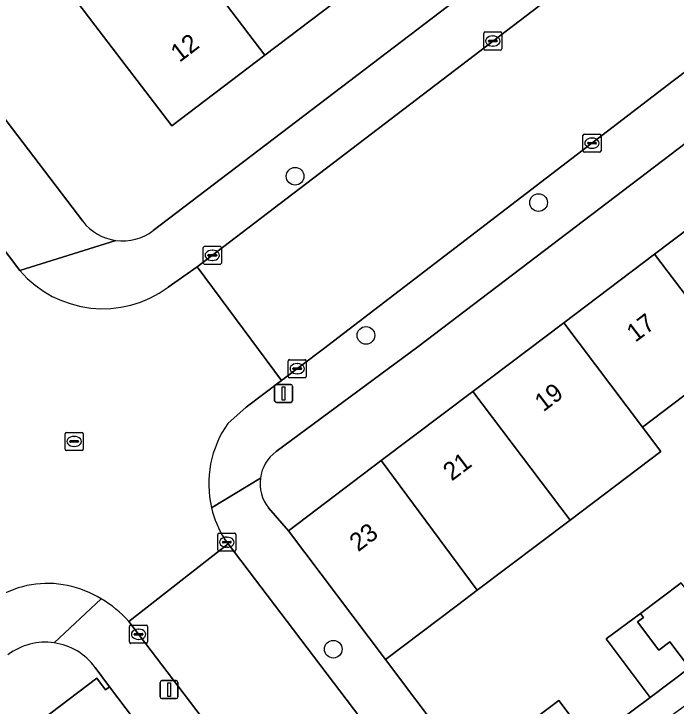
# Model space of a CAD drawing. Extents: x 160030 to 160839, y 385325 to 386450.
# Drawn here: x 160433.9 to 160470.59, y 385780.35 to 385818.69 of the extents above; entities that cross this region are included whole.
import ezdxf

# ---------------------------------------------------------------- set-up
doc = ezdxf.new("R2010")
doc.units = 0
for name, color, linetype in [('IMGEO_Boom', 7, 'Continuous'), ('IMGEO_Erf', 7, 'Continuous'), ('IMGEO_Kolk', 7, 'Continuous'), ('IMGEO_Lichtmast', 7, 'Continuous'), ('IMGEO_Muur', 7, 'Continuous'), ('IMGEO_Pand', 7, 'Continuous'), ('IMGEO_Pand_nummerreeks', 7, 'Continuous'), ('IMGEO_Rijbaan_lokaal_gesloten', 7, 'Continuous'), ('IMGEO_Rijbaan_lokaal_open', 7, 'Continuous'), ('IMGEO_Rioolput', 7, 'Continuous'), ('IMGEO_Voetpad_open', 7, 'Continuous')]:
    doc.layers.add(name, color=color, linetype=linetype)

msp = doc.modelspace()

# ---------------------------------------------------------------- linework, layer by layer
at = {"layer": 'IMGEO_Boom'}
for centre in [(160449.48, 385809.696), (160462.963, 385808.239), (160453.405, 385800.885), (160451.596, 385783.509)]:
    msp.add_circle(centre, 0.489, dxfattribs=at)
at = {"layer": 'IMGEO_Erf'}
for points in [[(160467.463, 385842.567), (160469.844, 385844.381), (160463.561, 385852.624), (160458.547, 385848.802), (160460.94, 385845.697), (160458.995, 385844.199), (160456.333, 385842.148), (160453.941, 385845.253), (160448.054, 385840.924), (160450.43, 385837.841), (160448.874, 385836.653), (160446.135, 385834.562), (160443.773, 385837.627), (160438.306, 385833.163), (160440.377, 385830.449), (160438.706, 385829.174), (160433.311, 385825.057), (160431.24, 385827.77), (160425.422, 385823.334), (160437.717, 385807.206)], [(160502.255, 385835.22), (160500, 385833.506), (160456.281, 385800.253), (160448.431, 385794.458)], [(160441.615, 385806.689), (160475.467, 385832.462)], [(160452.895, 385820.284), (160447.811, 385816.411), (160442.656, 385812.482), (160438.396, 385818.072), (160437.33, 385819.471)], [(160447.999, 385791.331), (160449.109, 385790.064), (160454.255, 385793.952), (160459.32, 385797.779), (160464.358, 385801.585), (160469.393, 385805.39), (160474.571, 385809.302)], [(160473.754, 385799.618), (160468.72, 385795.811), (160469.74, 385794.448), (160464.707, 385790.65), (160459.571, 385786.773), (160458.479, 385785.949), (160454.488, 385782.937), (160457.798, 385778.545), (160459.045, 385776.888), (160464.083, 385780.673), (160465.818, 385778.364), (160469.15, 385780.836), (160466.716, 385784.074), (160468.603, 385785.493), (160470.862, 385787.192)], [(160432.251, 385777.109), (160432.774, 385776.42), (160434.275, 385777.561), (160435.973, 385778.852), (160435.427, 385779.57), (160438.493, 385781.901), (160438.986, 385781.253), (160439.203, 385781.418), (160438.405, 385782.504)]]:
    msp.add_lwpolyline(points, dxfattribs=at)
for centre, radius, start, end in [((160439.928, 385808.909), 2.79, 217.6113, 262.4111), ((160439.926, 385808.905), 2.786, 262.4288, 307.3161), ((160449.754, 385792.68), 2.216, 126.6579, 172.092), ((160449.757, 385792.684), 2.218, 172.2024, 217.5914), ((160435.648, 385780.463), 3.434, 81.858, 127.1706), ((160435.647, 385780.47), 3.426, 36.4076, 81.8358)]:
    msp.add_arc(centre, radius, start, end, dxfattribs=at)
at = {"layer": 'IMGEO_Kolk'}
for p, q in [((160459.931, 385816.759), (160459.931, 385817.611)), ((160460.006, 385817.685), (160460.858, 385817.685)), ((160460.419, 385817.465), (160460.444, 385817.465)), ((160460.932, 385817.611), (160460.932, 385816.759)), ((160460.19, 385817.179), (160460.19, 385817.191)), ((160460.628, 385817.142), (160460.23, 385817.142)), ((160460.233, 385817.228), (160460.631, 385817.228)), ((160460.674, 385817.191), (160460.674, 385817.179)), ((160460.858, 385816.685), (160460.006, 385816.685)), ((160460.442, 385816.905), (160460.417, 385816.905)), ((160465.422, 385811.103), (160465.422, 385811.955)), ((160465.497, 385812.029), (160466.349, 385812.029)), ((160466.423, 385811.955), (160466.423, 385811.103)), ((160465.724, 385811.572), (160466.122, 385811.572)), ((160465.91, 385811.809), (160465.935, 385811.809)), ((160465.681, 385811.523), (160465.681, 385811.535)), ((160466.119, 385811.486), (160465.721, 385811.486)), ((160465.933, 385811.249), (160465.908, 385811.249)), ((160466.165, 385811.535), (160466.165, 385811.523)), ((160466.349, 385811.029), (160465.497, 385811.029)), ((160444.469, 385805.819), (160445.321, 385805.819)), ((160444.394, 385804.893), (160444.394, 385805.745)), ((160444.882, 385805.599), (160444.907, 385805.599)), ((160445.395, 385805.745), (160445.395, 385804.893)), ((160444.653, 385805.313), (160444.653, 385805.325)), ((160445.091, 385805.276), (160444.693, 385805.276)), ((160444.696, 385805.362), (160445.094, 385805.362)), ((160444.905, 385805.039), (160444.88, 385805.039)), ((160445.137, 385805.325), (160445.137, 385805.313)), ((160445.321, 385804.819), (160444.469, 385804.819)), ((160449.1, 385798.615), (160449.1, 385799.467)), ((160449.175, 385799.541), (160450.027, 385799.541)), ((160449.588, 385799.321), (160449.613, 385799.321)), ((160450.101, 385799.467), (160450.101, 385798.615)), ((160449.359, 385799.035), (160449.359, 385799.047)), ((160449.797, 385798.998), (160449.399, 385798.998)), ((160449.402, 385799.084), (160449.8, 385799.084)), ((160449.843, 385799.047), (160449.843, 385799.035)), ((160450.027, 385798.541), (160449.175, 385798.541)), ((160449.611, 385798.761), (160449.586, 385798.761)), ((160445.201, 385789.007), (160445.201, 385789.859)), ((160445.276, 385789.933), (160446.128, 385789.933)), ((160445.689, 385789.713), (160445.714, 385789.713)), ((160446.202, 385789.859), (160446.202, 385789.007)), ((160445.46, 385789.427), (160445.46, 385789.439)), ((160445.898, 385789.39), (160445.5, 385789.39)), ((160445.503, 385789.476), (160445.901, 385789.476)), ((160445.944, 385789.439), (160445.944, 385789.427)), ((160445.712, 385789.153), (160445.687, 385789.153)), ((160446.128, 385788.933), (160445.276, 385788.933)), ((160440.312, 385783.908), (160440.312, 385784.76)), ((160440.387, 385784.834), (160441.239, 385784.834)), ((160441.313, 385784.76), (160441.313, 385783.908)), ((160440.571, 385784.328), (160440.571, 385784.34)), ((160440.614, 385784.377), (160441.012, 385784.377)), ((160440.8, 385784.614), (160440.825, 385784.614)), ((160441.055, 385784.34), (160441.055, 385784.328)), ((160441.009, 385784.291), (160440.611, 385784.291)), ((160440.823, 385784.054), (160440.798, 385784.054)), ((160441.239, 385783.834), (160440.387, 385783.834))]:
    msp.add_line(p, q, dxfattribs=at)
for points in [[(160459.931, 385816.759), (160459.931, 385817.611)], [(160460.006, 385817.685), (160460.858, 385817.685)], [(160460.932, 385817.611), (160460.932, 385816.759)], [(160460.858, 385816.685), (160460.006, 385816.685)], [(160465.422, 385811.103), (160465.422, 385811.955)], [(160465.497, 385812.029), (160466.349, 385812.029)], [(160466.423, 385811.955), (160466.423, 385811.103)], [(160466.349, 385811.029), (160465.497, 385811.029)], [(160444.469, 385805.819), (160445.321, 385805.819)], [(160444.394, 385804.893), (160444.394, 385805.745)], [(160445.395, 385805.745), (160445.395, 385804.893)], [(160445.321, 385804.819), (160444.469, 385804.819)], [(160449.1, 385798.615), (160449.1, 385799.467)], [(160449.175, 385799.541), (160450.027, 385799.541)], [(160450.101, 385799.467), (160450.101, 385798.615)], [(160450.027, 385798.541), (160449.175, 385798.541)], [(160445.201, 385789.007), (160445.201, 385789.859)], [(160445.276, 385789.933), (160446.128, 385789.933)], [(160446.202, 385789.859), (160446.202, 385789.007)], [(160446.128, 385788.933), (160445.276, 385788.933)], [(160440.312, 385783.908), (160440.312, 385784.76)], [(160440.387, 385784.834), (160441.239, 385784.834)], [(160441.313, 385784.76), (160441.313, 385783.908)], [(160441.239, 385783.834), (160440.387, 385783.834)]]:
    msp.add_lwpolyline(points, dxfattribs=at)
for centre, radius, start, end in [((160460.008, 385817.609), 0.0765, 91.552, 178.448), ((160460.008, 385817.609), 0.0765, 91.552, 178.448), ((160460.856, 385817.609), 0.0765, 1.552, 88.448), ((160460.856, 385817.609), 0.0765, 1.552, 88.448), ((160460.23, 385817.188), 0.0403, 85.8775, 175.7526), ((160460.227, 385817.178), 0.0366, 178.938, 274.7102), ((160460.631, 385817.185), 0.043, 264.8664, 352.4533), ((160460.635, 385817.19), 0.0386, 1.7309, 96.639), ((160460.008, 385816.761), 0.0765, 181.552, 268.448), ((160460.008, 385816.761), 0.0765, 181.552, 268.448), ((160460.856, 385816.761), 0.0765, 271.552, 358.448), ((160460.856, 385816.761), 0.0765, 271.552, 358.448), ((160465.499, 385811.953), 0.0765, 91.552, 178.448), ((160465.499, 385811.953), 0.0765, 91.552, 178.448), ((160466.347, 385811.953), 0.0765, 1.552, 88.448), ((160466.347, 385811.953), 0.0765, 1.552, 88.448), ((160465.721, 385811.532), 0.0403, 85.8775, 175.7526), ((160466.126, 385811.534), 0.0386, 1.7309, 96.639), ((160465.718, 385811.522), 0.0366, 178.938, 274.7102), ((160466.122, 385811.529), 0.043, 264.8664, 352.4533), ((160465.499, 385811.105), 0.0765, 181.552, 268.448), ((160465.499, 385811.105), 0.0765, 181.552, 268.448), ((160466.347, 385811.105), 0.0765, 271.552, 358.448), ((160466.347, 385811.105), 0.0765, 271.552, 358.448), ((160444.471, 385805.743), 0.0765, 91.552, 178.448), ((160444.471, 385805.743), 0.0765, 91.552, 178.448), ((160445.319, 385805.743), 0.0765, 1.552, 88.448), ((160445.319, 385805.743), 0.0765, 1.552, 88.448), ((160444.693, 385805.322), 0.0403, 85.8775, 175.7526), ((160444.69, 385805.312), 0.0366, 178.938, 274.7102), ((160445.094, 385805.319), 0.043, 264.8664, 352.4533), ((160445.098, 385805.324), 0.0386, 1.7309, 96.639), ((160444.471, 385804.895), 0.0765, 181.552, 268.448), ((160444.471, 385804.895), 0.0765, 181.552, 268.448), ((160445.319, 385804.895), 0.0765, 271.552, 358.448), ((160445.319, 385804.895), 0.0765, 271.552, 358.448), ((160449.177, 385799.465), 0.0765, 91.552, 178.448), ((160449.177, 385799.465), 0.0765, 91.552, 178.448), ((160450.025, 385799.465), 0.0765, 1.552, 88.448), ((160450.025, 385799.465), 0.0765, 1.552, 88.448), ((160449.399, 385799.044), 0.0403, 85.8775, 175.7526), ((160449.396, 385799.034), 0.0366, 178.938, 274.7102), ((160449.8, 385799.041), 0.043, 264.8664, 352.4533), ((160449.804, 385799.046), 0.0386, 1.7309, 96.639), ((160449.177, 385798.617), 0.0765, 181.552, 268.448), ((160449.177, 385798.617), 0.0765, 181.552, 268.448), ((160450.025, 385798.617), 0.0765, 271.552, 358.448), ((160450.025, 385798.617), 0.0765, 271.552, 358.448), ((160445.278, 385789.857), 0.0765, 91.552, 178.448), ((160445.278, 385789.857), 0.0765, 91.552, 178.448), ((160446.126, 385789.857), 0.0765, 1.552, 88.448), ((160446.126, 385789.857), 0.0765, 1.552, 88.448), ((160445.5, 385789.436), 0.0403, 85.8775, 175.7526), ((160445.497, 385789.426), 0.0366, 178.938, 274.7102), ((160445.901, 385789.433), 0.043, 264.8664, 352.4533), ((160445.905, 385789.438), 0.0386, 1.7309, 96.639), ((160445.278, 385789.009), 0.0765, 181.552, 268.448), ((160445.278, 385789.009), 0.0765, 181.552, 268.448), ((160446.126, 385789.009), 0.0765, 271.552, 358.448), ((160446.126, 385789.009), 0.0765, 271.552, 358.448), ((160440.389, 385784.758), 0.0765, 91.552, 178.448), ((160440.389, 385784.758), 0.0765, 91.552, 178.448), ((160441.237, 385784.758), 0.0765, 1.552, 88.448), ((160441.237, 385784.758), 0.0765, 1.552, 88.448), ((160440.611, 385784.337), 0.0403, 85.8775, 175.7526), ((160441.016, 385784.339), 0.0386, 1.7309, 96.639), ((160440.608, 385784.327), 0.0366, 178.938, 274.7102), ((160441.012, 385784.334), 0.043, 264.8664, 352.4533), ((160440.389, 385783.91), 0.0765, 181.552, 268.448), ((160440.389, 385783.91), 0.0765, 181.552, 268.448), ((160441.237, 385783.91), 0.0765, 271.552, 358.448), ((160441.237, 385783.91), 0.0765, 271.552, 358.448)]:
    msp.add_arc(centre, radius, start, end, dxfattribs=at)
for centre, major_axis, ratio, start_param, end_param in [((160460.418, 385817.185), (-0.387, 0.002), 0.722429, 4.712389, 7.853982), ((160460.443, 385817.185), (-0.39, 0.002), 0.717154, 1.570796, 4.712389), ((160465.909, 385811.529), (-0.387, 0.002), 0.722429, 4.712389, 7.853982), ((160465.934, 385811.529), (-0.39, 0.002), 0.717154, 1.570796, 4.712389), ((160444.881, 385805.319), (-0.387, 0.002), 0.722429, 4.712389, 7.853982), ((160444.906, 385805.319), (-0.39, 0.002), 0.717154, 1.570796, 4.712389), ((160449.587, 385799.041), (-0.387, 0.002), 0.722429, 4.712389, 7.853982), ((160449.612, 385799.041), (-0.39, 0.002), 0.717154, 1.570796, 4.712389), ((160445.688, 385789.433), (-0.387, 0.002), 0.722429, 4.712389, 7.853982), ((160445.713, 385789.433), (-0.39, 0.002), 0.717154, 1.570796, 4.712389), ((160440.799, 385784.334), (-0.387, 0.002), 0.722429, 4.712389, 7.853982), ((160440.824, 385784.334), (-0.39, 0.002), 0.717154, 1.570796, 4.712389)]:
    msp.add_ellipse(centre, major_axis=major_axis, ratio=ratio, start_param=start_param, end_param=end_param, dxfattribs=at)
at = {"layer": 'IMGEO_Lichtmast'}
for p, q in [((160448.447, 385798.17), (160449.237, 385798.17)), ((160449.237, 385798.17), (160448.447, 385798.17)), ((160448.347, 385797.27), (160448.347, 385798.07)), ((160448.347, 385798.07), (160448.347, 385797.27)), ((160449.337, 385798.07), (160449.337, 385797.27)), ((160449.337, 385797.27), (160449.337, 385798.07)), ((160449.237, 385797.17), (160448.447, 385797.17)), ((160448.447, 385797.17), (160449.237, 385797.17)), ((160442.004, 385780.873), (160442.004, 385781.673)), ((160442.004, 385781.673), (160442.004, 385780.873)), ((160442.104, 385781.773), (160442.894, 385781.773)), ((160442.894, 385781.773), (160442.104, 385781.773)), ((160442.994, 385781.673), (160442.994, 385780.873)), ((160442.994, 385780.873), (160442.994, 385781.673)), ((160442.894, 385780.773), (160442.104, 385780.773)), ((160442.104, 385780.773), (160442.894, 385780.773))]:
    msp.add_line(p, q, dxfattribs=at)
for points in [[(160448.767, 385798.045), (160448.917, 385798.045), (160448.917, 385797.295), (160448.767, 385797.295), (160448.767, 385798.045)], [(160442.424, 385781.648), (160442.574, 385781.648), (160442.574, 385780.898), (160442.424, 385780.898), (160442.424, 385781.648)]]:
    msp.add_lwpolyline(points, dxfattribs=at)
for centre, start, end in [((160448.447, 385798.07), 90, 180), ((160448.447, 385798.07), 90, 180), ((160449.237, 385798.07), 0, 90), ((160449.237, 385798.07), 360, 90), ((160448.447, 385797.27), 180, 270), ((160448.447, 385797.27), 180, 270), ((160449.237, 385797.27), 270, 0), ((160449.237, 385797.27), 270, 0), ((160442.104, 385781.673), 90, 180), ((160442.104, 385781.673), 90, 180), ((160442.894, 385781.673), 0, 90), ((160442.894, 385781.673), 360, 90), ((160442.104, 385780.873), 180, 270), ((160442.104, 385780.873), 180, 270), ((160442.894, 385780.873), 270, 0), ((160442.894, 385780.873), 270, 0)]:
    msp.add_arc(centre, 0.1, start, end, dxfattribs=at)
at = {"layer": 'IMGEO_Muur'}
msp.add_lwpolyline([(160454.488, 385782.937), (160457.798, 385778.545)], dxfattribs=at)
at = {"layer": 'IMGEO_Pand'}
for points in [[(160448.635, 385825.874), (160447.507, 385827.354), (160444.949, 385825.405), (160446.077, 385823.925), (160443.551, 385822), (160447.811, 385816.411), (160452.895, 385820.284)], [(160443.551, 385822), (160442.485, 385823.4), (160442.218, 385823.197), (160440.264, 385825.761), (160435.376, 385822.036), (160437.33, 385819.471), (160438.396, 385818.072), (160442.656, 385812.482), (160447.811, 385816.411)], [(160473.754, 385799.618), (160478.951, 385803.548), (160477.599, 385805.324), (160474.571, 385809.302), (160469.393, 385805.39)], [(160468.72, 385795.811), (160473.754, 385799.618), (160469.393, 385805.39), (160464.358, 385801.585)], [(160464.707, 385790.65), (160469.74, 385794.448), (160468.72, 385795.811), (160464.358, 385801.585), (160459.32, 385797.779)], [(160459.32, 385797.779), (160454.255, 385793.952), (160459.571, 385786.773), (160464.707, 385790.65)], [(160454.488, 385782.937), (160458.479, 385785.949), (160459.571, 385786.773), (160454.255, 385793.952), (160449.109, 385790.064)], [(160468.603, 385785.493), (160468.772, 385785.27), (160468.439, 385785.019), (160469.623, 385783.448), (160470.237, 385783.911), (160471.324, 385782.471), (160473.297, 385783.955), (160470.862, 385787.192)], [(160468.603, 385785.493), (160466.716, 385784.074), (160469.15, 385780.836), (160471.324, 385782.471), (160470.237, 385783.911), (160469.623, 385783.448), (160468.439, 385785.019), (160468.772, 385785.27)], [(160439.203, 385781.418), (160438.986, 385781.253), (160438.493, 385781.901), (160435.427, 385779.57), (160435.973, 385778.852), (160434.275, 385777.561), (160439.255, 385771.019), (160444.229, 385774.806)], [(160464.083, 385780.673), (160459.045, 385776.888), (160460.78, 385774.579), (160465.818, 385778.364)]]:
    msp.add_lwpolyline(points, close=True, dxfattribs=at)
at = {"layer": 'IMGEO_Rijbaan_lokaal_gesloten'}
msp.add_lwpolyline([(160495.699, 385834.509), (160496.571, 385836.664), (160497.067, 385837.411), (160493.352, 385842.337), (160487.975, 385838.222), (160485.988, 385836.666), (160479.417, 385831.661), (160477.302, 385830.05), (160469.047, 385823.762), (160444.062, 385804.681), (160448.723, 385798.382), (160451.05, 385800.142), (160470.421, 385814.975), (160486.246, 385826.946), (160488.303, 385828.547), (160494.77, 385833.394)], dxfattribs=at)
at = {"layer": 'IMGEO_Rijbaan_lokaal_open'}
for points in [[(160434.231, 385804.47), (160433.017, 385806.06), (160427.481, 385801.96), (160428.538, 385800.565)], [(160445.752, 385796.007), (160446.769, 385796.904), (160448.723, 385798.382), (160444.062, 385804.681), (160442.445, 385803.552)], [(160440.269, 385785.051), (160445.768, 385789.344), (160445.562, 385789.615)]]:
    msp.add_lwpolyline(points, dxfattribs=at)
msp.add_lwpolyline([(160475.667, 385750), (160461.3, 385768.906), (160459.341, 385771.483), (160458.532, 385772.547), (160456.328, 385775.448), (160445.768, 385789.344), (160440.269, 385785.051), (160460.541, 385758.433), (160466.313, 385750.996), (160466.344, 385750.961), (160476.157, 385738.065), (160476.427, 385737.611), (160498.422, 385708.377), (160500, 385706.302), (160500.083, 385706.193), (160505.746, 385710.546), (160503.974, 385712.848), (160500, 385718.016), (160497.228, 385721.62), (160490.796, 385730.087)], close=True, dxfattribs=at)
for centre, radius, start, end in [((160438.833, 385808.444), 6.081, 220.8101, 306.436), ((160450.508, 385792.666), 5.812, 144.9115, 193.2756), ((160450.556, 385792.69), 5.865, 193.3946, 211.6173), ((160435.762, 385781.798), 5.352, 77.9963, 121.096), ((160435.475, 385780.735), 6.452, 59.5342, 77.4661), ((160435.469, 385780.733), 6.457, 41.9729, 59.4975)]:
    msp.add_arc(centre, radius, start, end, dxfattribs=at)
at = {"layer": 'IMGEO_Rioolput'}
for p, q in [((160436.816, 385795.513), (160437.668, 385795.513)), ((160436.741, 385794.587), (160436.741, 385795.439)), ((160437.229, 385795.293), (160437.254, 385795.293)), ((160437.742, 385795.439), (160437.742, 385794.587)), ((160437, 385795.007), (160437, 385795.019)), ((160437.438, 385794.97), (160437.04, 385794.97)), ((160437.043, 385795.056), (160437.441, 385795.056)), ((160437.252, 385794.733), (160437.227, 385794.733)), ((160437.484, 385795.019), (160437.484, 385795.007)), ((160437.668, 385794.513), (160436.816, 385794.513))]:
    msp.add_line(p, q, dxfattribs=at)
for points in [[(160436.816, 385795.513), (160437.668, 385795.513)], [(160436.741, 385794.587), (160436.741, 385795.439)], [(160437.742, 385795.439), (160437.742, 385794.587)], [(160437.668, 385794.513), (160436.816, 385794.513)]]:
    msp.add_lwpolyline(points, dxfattribs=at)
for centre, radius, start, end in [((160436.818, 385795.437), 0.0765, 91.552, 178.448), ((160436.818, 385795.437), 0.0765, 91.552, 178.448), ((160437.666, 385795.437), 0.0765, 1.552, 88.448), ((160437.666, 385795.437), 0.0765, 1.552, 88.448), ((160437.04, 385795.016), 0.0403, 85.8775, 175.7526), ((160437.037, 385795.006), 0.0366, 178.938, 274.7102), ((160437.441, 385795.013), 0.043, 264.8664, 352.4533), ((160437.445, 385795.018), 0.0386, 1.7309, 96.639), ((160436.818, 385794.589), 0.0765, 181.552, 268.448), ((160436.818, 385794.589), 0.0765, 181.552, 268.448), ((160437.666, 385794.589), 0.0765, 271.552, 358.448), ((160437.666, 385794.589), 0.0765, 271.552, 358.448)]:
    msp.add_arc(centre, radius, start, end, dxfattribs=at)
for centre, major_axis, ratio, start_param, end_param in [((160437.228, 385795.013), (-0.387, 0.002), 0.722429, 4.712389, 7.853982), ((160437.253, 385795.013), (-0.39, 0.002), 0.717154, 1.570796, 4.712389)]:
    msp.add_ellipse(centre, major_axis=major_axis, ratio=ratio, start_param=start_param, end_param=end_param, dxfattribs=at)
at = {"layer": 'IMGEO_Voetpad_open'}
for points in [[(160502.491, 385852.872), (160500, 385851.029), (160498.965, 385850.262), (160496.43, 385848.363), (160495.073, 385847.335), (160493.476, 385846.124), (160480.111, 385835.996), (160477.606, 385834.085), (160475.467, 385832.462), (160441.615, 385806.689)], [(160448.431, 385794.458), (160456.281, 385800.253), (160500, 385833.506)], [(160494.77, 385833.394), (160488.303, 385828.547), (160486.246, 385826.946), (160470.421, 385814.975), (160451.05, 385800.142), (160448.723, 385798.382), (160446.769, 385796.904), (160445.752, 385796.007)], [(160442.445, 385803.552), (160444.062, 385804.681), (160469.047, 385823.762), (160477.302, 385830.05)], [(160437.717, 385807.206), (160425.422, 385823.334)], [(160431.721, 385807.759), (160432.182, 385807.154), (160433.017, 385806.06), (160434.231, 385804.47), (160439.559, 385806.143)], [(160439.559, 385806.143), (160434.231, 385804.47)], [(160447.559, 385792.985), (160444.851, 385791.331)], [(160444.851, 385791.331), (160447.559, 385792.985)], [(160481.191, 385750), (160475.179, 385757.921), (160474.015, 385757.029), (160473.462, 385757.762), (160467.371, 385765.845), (160463.414, 385771.091), (160461.6, 385773.499), (160460.78, 385774.579), (160459.045, 385776.888), (160457.798, 385778.545), (160454.488, 385782.937), (160449.109, 385790.064), (160447.999, 385791.331)], [(160445.562, 385789.615), (160445.768, 385789.344), (160456.328, 385775.448), (160456.727, 385775.748), (160458.931, 385772.847), (160458.532, 385772.547), (160459.341, 385771.483), (160459.739, 385771.785), (160461.698, 385769.208), (160461.3, 385768.906), (160475.667, 385750), (160490.796, 385730.087)], [(160436.134, 385783.862), (160438.746, 385786.296)], [(160438.746, 385786.296), (160436.134, 385783.862)], [(160466.313, 385750.996), (160460.541, 385758.433), (160440.269, 385785.051)], [(160438.405, 385782.504), (160439.203, 385781.418), (160444.229, 385774.806), (160447.89, 385769.906), (160450.046, 385767.065), (160451.094, 385765.697), (160457.084, 385757.875), (160462.128, 385751.241), (160462.97, 385750), (160463.508, 385749.206), (160467.067, 385744.737)]]:
    msp.add_lwpolyline(points, dxfattribs=at)
msp.add_lwpolyline([(160470.904, 385780.254), (160477.138, 385784.981), (160476.218, 385786.152), (160475.124, 385785.329), (160473.297, 385783.955), (160471.324, 385782.471), (160469.15, 385780.836), (160465.818, 385778.364), (160460.78, 385774.579), (160461.6, 385773.499), (160466.358, 385776.953), (160466.738, 385776.449), (160467.445, 385777.001), (160467.084, 385777.48)], close=True, dxfattribs=at)
for centre, radius, start, end in [((160439.928, 385808.909), 2.79, 217.6113, 262.4111), ((160439.926, 385808.905), 2.786, 262.4288, 307.3161), ((160438.833, 385808.444), 6.081, 220.8101, 306.436), ((160450.508, 385792.666), 5.812, 144.9115, 193.2756), ((160449.754, 385792.68), 2.216, 126.6579, 172.092), ((160449.757, 385792.684), 2.218, 172.2024, 217.5914), ((160450.556, 385792.69), 5.865, 193.3946, 211.6173), ((160435.762, 385781.798), 5.352, 77.9963, 121.096), ((160435.475, 385780.735), 6.452, 59.5342, 77.4661), ((160435.469, 385780.733), 6.457, 41.9729, 59.4975), ((160435.648, 385780.463), 3.434, 81.858, 127.1706), ((160435.647, 385780.47), 3.426, 36.4076, 81.8358)]:
    msp.add_arc(centre, radius, start, end, dxfattribs=at)

# ---------------------------------------------------------------- texts
at = {"layer": 'IMGEO_Pand_nummerreeks'}
for s, rotation, p in [('12', 37.311, (160443.073, 385815.969)), ('17', 37.0731, (160468.323, 385800.47)), ('19', 37.0731, (160463.23, 385796.622)), ('21', 37.0731, (160458.156, 385792.789)), ('23', 37.0731, (160452.973, 385788.873))]:
    msp.add_text(s, height=1, rotation=rotation, dxfattribs=at).set_placement(p)

doc.saveas('drawing.dxf')
